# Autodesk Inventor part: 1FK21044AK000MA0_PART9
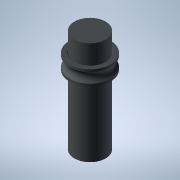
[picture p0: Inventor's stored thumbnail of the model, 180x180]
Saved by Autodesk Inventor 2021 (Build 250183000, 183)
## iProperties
Created: 2025-04
Part Number: 1FK21044AK000MA0_PART9
Material: Generic
Catalog Web Link: www.3dfindit.com
Description: -Servo synchronous motor
Document SubType Name: Modeling
Designer: psAdmin
Mass: 18.6788 g
Surface Area: 52.316 cm^2
Volume: 18.6788 cm^3
Density: 1 g/cm^3
Appearance: PSOLRGB-212-217-219
Category: PARTsolutions
Title: 1FK21044AK000MA0_PART9
Author: Cadenas PARTsolutions
Comments: Servo synchronous motor
Sending System: PARTsolutions
Preprocessor: ST-DEVELOPER v19.3
PSOL_IDENT_0: {$CADENAS_DATA/23d-libs/siemens_ag/_cat_/87/f4/1fk21044ak000ma0.prj},213 {VTYP=3D},{NB=1FK21044AK000
PSOL_IDENT_1: MA0_PART9},{LINA=1FK21044AK000MA0_PART9},{NN=1FK21044AK000MA0_PART9},{NOPRJ=TRUE},{DATE=19.08.2025 1
PSOL_IDENT_2: 4:00:48},{GEOMDATE=30.07.2025 02:00:50},{VERSION=},{LINEID=10},{WBVAR=},{WBNUMERIC=}  {NB=1FK21044AK
PSOL_IDENT_3: 000MA0_PART9},{LINA=1FK21044AK000MA0_PART9},{KT=DUMMY},{PREVIEW=../../../_pool_/cb/72/p_d211_xx_0043
PSOL_IDENT_4: 4j.png},{DESCSHORT=SIMOTICS S-1FK2 HD, SINAMICS S210 3AC 400V-480V, 0.95 Nm, 6000 rpm},{DESCLONG=SIM
PSOL_IDENT_5: OTICS S-1FK2 HD servo motor M0=1.27 Nm; PN = 0.6 kW at nN=6000 rpm (380-480 V); PN = 0.4 kW at nN=30
PSOL_IDENT_6: 00 rpm (200-240 V); degree of protection IP64; cylindrical shaft D19x40mm; absolute encoder 22-bit +
PSOL_IDENT_7: 12-bit multiturn (encoder AM22DQC); with OCC interface; plug size M17, rotatable; SIMOTICS S-1FK2 s
PSOL_IDENT_8: ervomotorfor a wide range of uses in industrial environments. SIMOTICS S‑1FK2 servomotors are compac
PSOL_IDENT_9: t synchronous motors with a high dynamic performance that set themselves apart as a result of their
PSOL_IDENT_10: high power density, degree of protection and overload capability. The motors are available in two va
PSOL_IDENT_11: riants: as High Dynamic variant (highest dynamic performance as a result of the low intrinsic moment
PSOL_IDENT_12: of inertia for applications demanding a high dynamic performance with low moved masses) - and as Co
PSOL_IDENT_13: mpact variant (precise and stable closed-loop control for medium up to large moved masses as a resul
PSOL_IDENT_14: t of a medium intrinsic moment of inertia). SIMOTICSS‑1FK2 servomotors fully exploit their strengths
PSOL_IDENT_15: in a system with the SINAMICSS210 frequency converter and simple connection using the one cable con
PSOL_IDENT_16: nection (OCC). Advantages include the short control and positioning times, fast and precise correcti
PSOL_IDENT_17: on of disturbing quantities as well as stable control with a high dynamic performance. The servo mot
PSOL_IDENT_18: ors can be configured to address a wide range of requirements. For example with and without holding
PSOL_IDENT_19: brake, IP64 or IP65 degree of protection, singleturn or multiturn absolute encoders - to name just a
PSOL_IDENT_20: few. Further, the servomotors are available in different shaft heights extending from 20 to 100. A
PSOL_IDENT_21: shaft sealing ring is available to achieve an IP65 degree of protection and for subsequent mounting
PSOL_IDENT_22: at the motor or as spare part. SIMOTICS - the optimum motor for each and every motion control applic
PSOL_IDENT_23: ation.},{INTNO=195125056312},{SUPPLIERALTNO=1FK2104-4AK00-0MA0},{MANUID=1FK21044AK000MA0},{MANUNAME=
PSOL_IDENT_24: Siemens},{MANUTYPEDESC=Synchronous motor 1FK2-HD 1,27 Nm},{AAU732=SIMOTICS},{AAO057=S-1FK2},{AAU734=
PSOL_IDENT_25: SIMOTICS S-1FK2 HD servo motor M0=1.27 Nm; PN = 0.6 kW at nN=6000 rpm (380-480 V); PN = 0.4 kW at nN=
PSOL_IDENT_26: 3000 rpm (200-240 V); degree of protection IP64; cylindrical shaft D19x40mm; absolute encoder 22-bit
PSOL_IDENT_27: + 12-bit multiturn (encoder AM22DQC); with OCC interface; plug size M17, rotatable;},{AAW338=Synchr
PSOL_IDENT_28: onous motor 1FK2-HD 1,27 Nm},{AAO742=SIMOTICS},{AAO663=4042948690994},{NOCUPEROU=1},{PRICEQUANTITY=1
PSOL_IDENT_29: },{QUANTITYMIN=1},{QUANTITYINT=1},{CTN=85015100},{COO=DE},{AAO676=1FK2104-4AK00-0MA0},{AAO677=Siemen
PSOL_IDENT_30: s AG},{ORDERUNIT=C62},{CONTENTUNIT=C62}
NB: 1FK21044AK000MA0_PART9
NT: Servo synchronous motor
NBSYN: $MANUID._PART9
LINA: 1FK21044AK000MA0_PART9
CATALOG: SIEMENS
PREVIEW: ../../../_pool_/cb/72/p_d211_xx_00434j.png
DESCSHORT: SIMOTICS S-1FK2 HD, SINAMICS S210 3AC 400V-480V, 0.95 Nm, 6000 rpm
DESCLONG: SIMOTICS S-1FK2 HD servo motor M0=1.27 Nm; PN = 0.6 kW at nN=6000 rpm (380-480 V); PN = 0.4 kW at nN=3000 rpm (200-240 V); degree of protection IP64; cylindrica
INTNO: 195125056312
SUPPLIERALTNO: 1FK2104-4AK00-0MA0
MANUID: 1FK21044AK000MA0
MANUNAME: Siemens
MANUTYPEDESC: Synchronous motor 1FK2-HD 1,27 Nm
AAU732: SIMOTICS
AAO057: S-1FK2
AAU734: SIMOTICS S-1FK2 HD servo motor M0=1.27 Nm; PN = 0.6 kW at nN=6000 rpm (380-480 V); PN = 0.4 kW at nN=3000 rpm (200-240 V); degree of protection IP64; cylindrica
AAW338: Synchronous motor 1FK2-HD 1,27 Nm
AAO742: SIMOTICS
AAO663: 4042948690994.0
NOCUPEROU: 1
PRICEQUANTITY: 1
QUANTITYMIN: 1
QUANTITYINT: 1
CTN: 85015100
COO: DE
ARTICLENO: 1FK21044AK000MA0_PART9
BOMINFO: 1FK21044AK000MA0_PART9
CREATOR: CADENAS GmbH
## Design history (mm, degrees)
feature "2025_04_17_15_37_40_0588"
body "Solid1"
